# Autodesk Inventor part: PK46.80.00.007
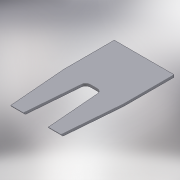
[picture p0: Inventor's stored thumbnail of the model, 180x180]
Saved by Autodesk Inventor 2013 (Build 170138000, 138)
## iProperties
Shininess: 64.0
Length Units: 11269
Angle Units: 11279
Time Units: 11290
Mass Units: 11283
Length Display Precision: 3
Angle Display Precision: 2
Compacted: True
Part Number: PK46.80.00.007
Document SubType Name: Modeling
Created: 2005-01
Material: Steel, Mild
Designer: SAlex
Manufacturer: Standard
Standards Organization: Custom
Density: 7.86 g/cm^3
Mass: 25478.1 g
Surface Area: 4491.32 cm^2
Volume: 3241.49 cm^3
Density: 0.0
Volumn: 0.0
Area: 0.0
PropertySet Name: Model Information
Control State: 0
Master: False
Checked Out: False
Checked Out Date: 2008-10-15
Last Check In Date: 2008-10-15
Author: SAlex
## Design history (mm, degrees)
sketch "Sketch1"
  geometry: L1 (0, 0)-(0, -320); L2 (0, -320)-(30, -690); L3 (30, -690)-(110, -690); L4 (110, -690)-(140, -320); L5 (140, -320)-(240, -320); L6 (240, -320)-(270, -690); L7 (270, -690)-(350, -690); L8 (350, -690)-(380, -320); L9 (380, -320)-(380, 0); L10 (380, 0)-(0, 0)
  constraints: 20 end point, 3 parallel, 2 collinear, 2 equal length, 1 perpendicular, 1 vertical, 1 other
  dimensions: "d0" = 380 distance of L9.end L1.start; "d1" = 690 distance between parallel lines of L10 L7; "d2" = 320 distance between parallel lines of L5 L10; "d3" = 320 distance of L8.end L9.end; "d4" = 80 distance of L6.end L7.end; "d5" = 80 distance of L2.end L3.end; "d6" = 100 distance of L4.end L5.end; "d7" = 140 distance from line of L5.end L9; "d8" = 30 distance from line of L7.end L9
extrude "Extrusion1" new body sketch "Sketch1" distance "d9" = 16; taper "d10" = 0 deg
fillet "Fillet1" dims "d11" = 30
chamfer "Chamfer1" distance "d12" = 12; stored, may be unused: second distance "d13" = 2, angle "d14" = 45 deg
body "Solid1"
